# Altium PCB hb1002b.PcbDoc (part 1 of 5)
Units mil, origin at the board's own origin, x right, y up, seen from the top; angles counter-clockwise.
Board outline 2756 x 3549 mil, 2 copper layers (Top Layer, Bottom Layer); 120 components, 136 nets, 498 pads, 328 vias.
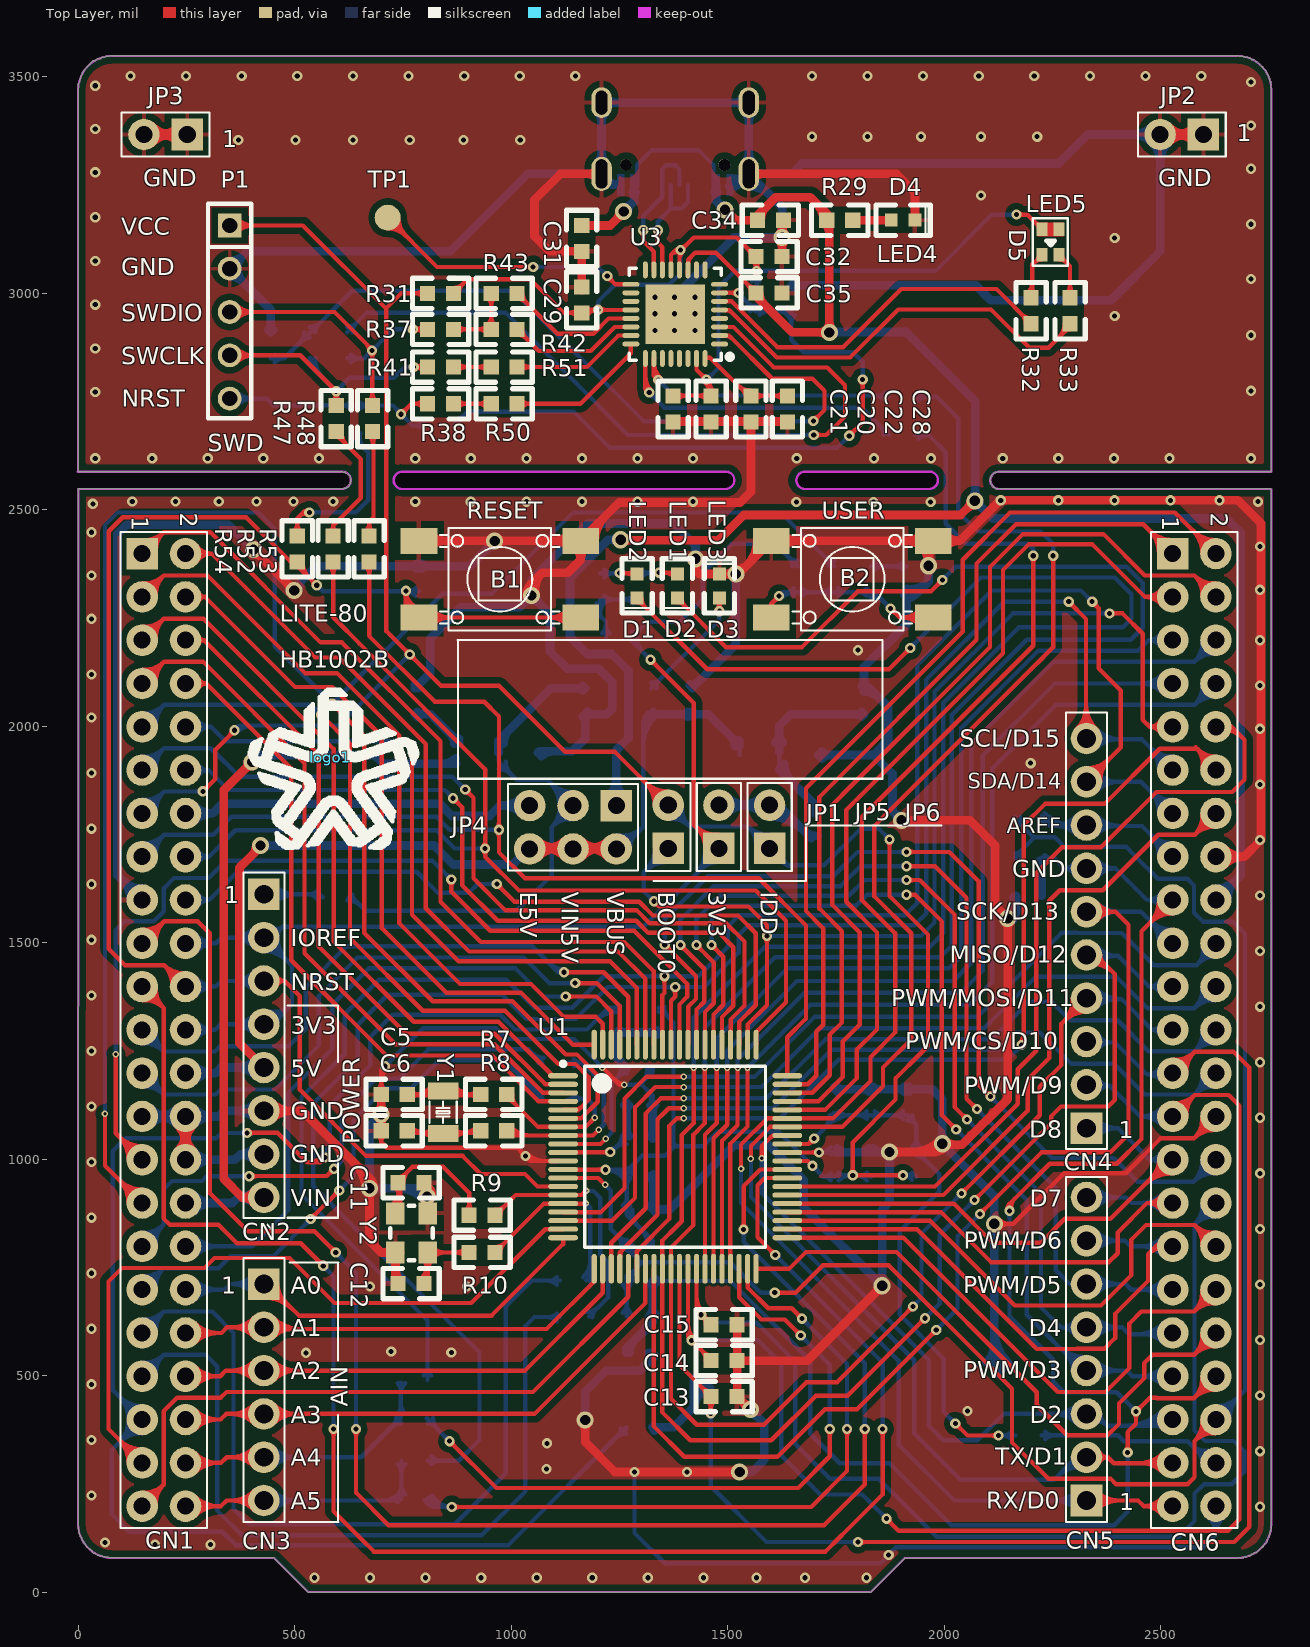
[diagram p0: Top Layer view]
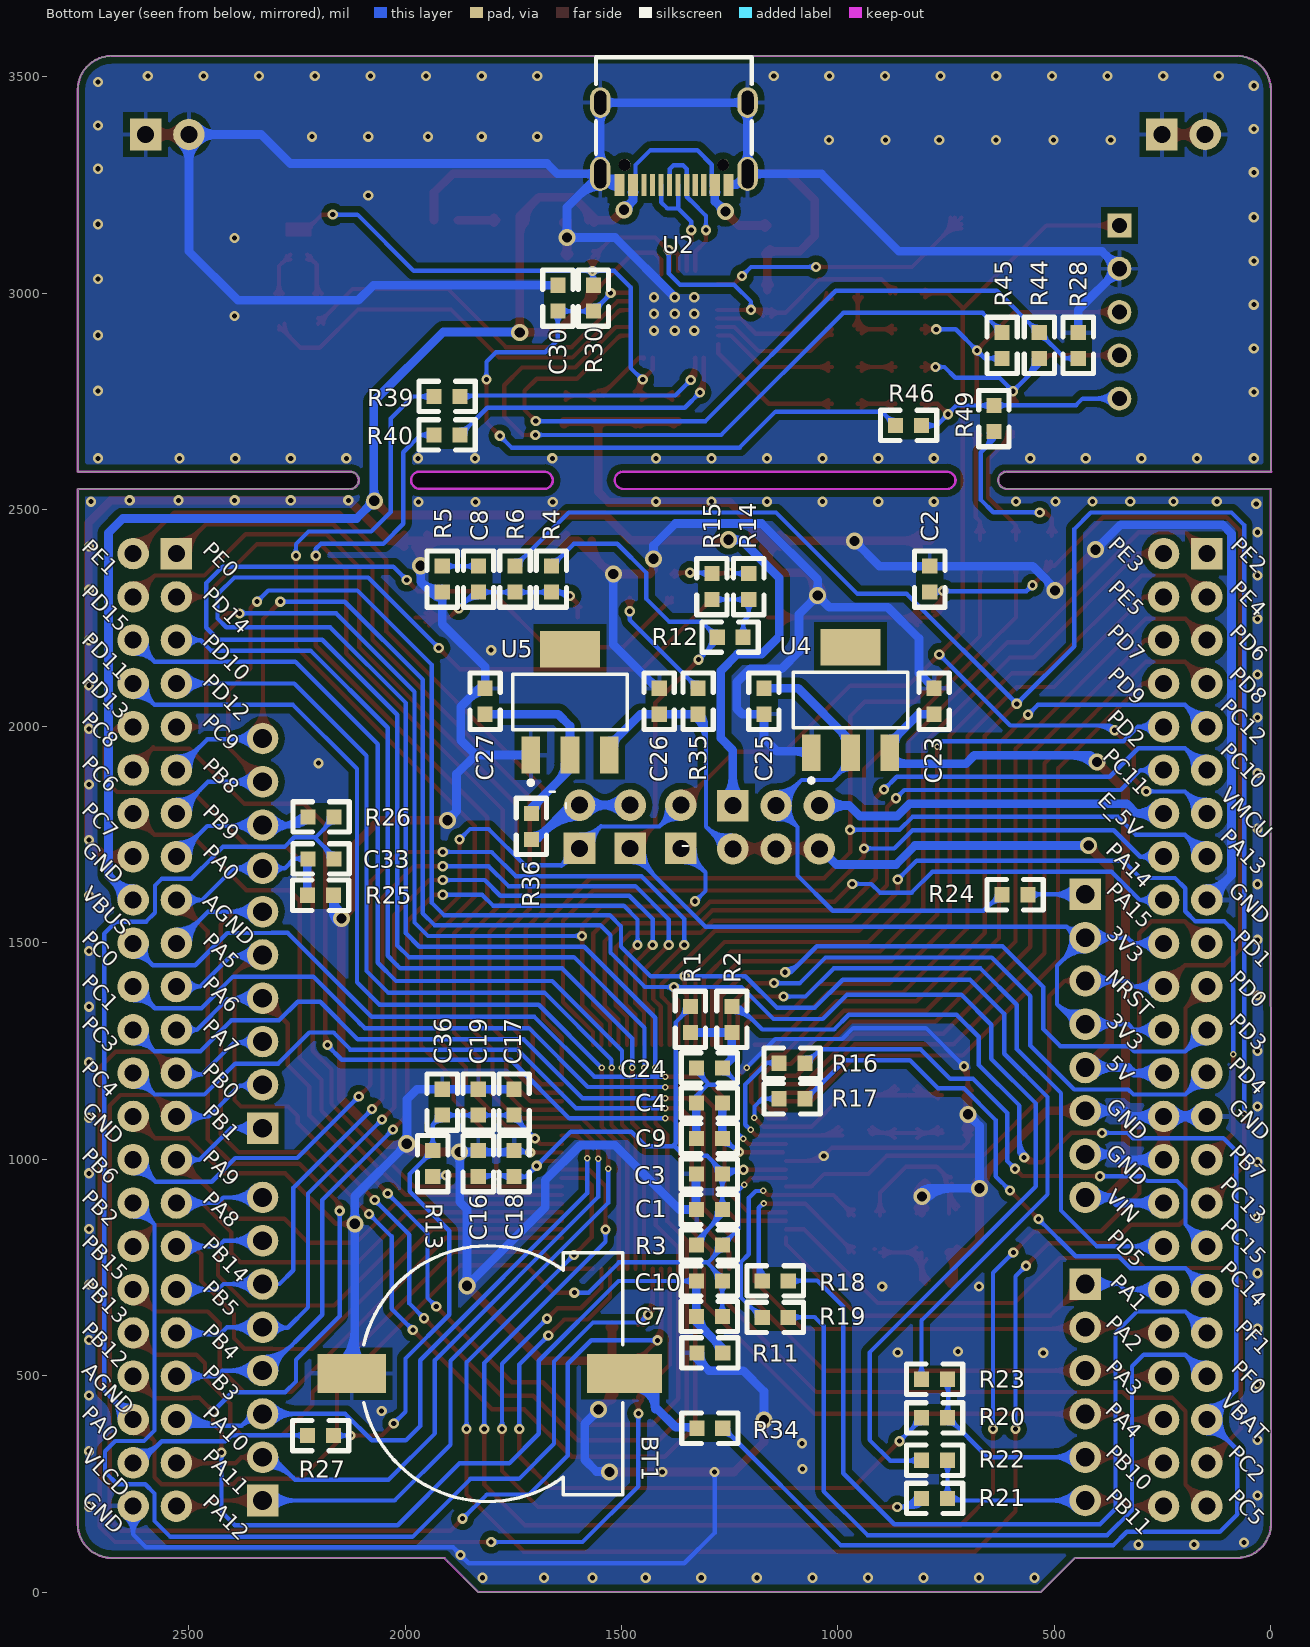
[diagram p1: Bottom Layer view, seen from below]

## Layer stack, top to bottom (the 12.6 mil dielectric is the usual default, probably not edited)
Top Layer: signal copper 1.4
Dielectric: dielectric 12.6, FR-4, Dk 4.8
Bottom Layer: signal copper 1.4

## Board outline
76,3549 2675,3549 2680,3549 2681,3548 2685,3548 2690,3548 2691,3547 2693,3547 2695,3547 2696,3546 2697,3545 2700,3545 2702,3545 2703,3544 2704,3543 2706,3543 2708,3543 2709,3542 2711,3540 2713,3540 2716,3540 2718,3538 2721,3535 2722,3535 2723,3535 2726,3532 2730,3528 2733,3525 2735,3523 2736,3523 2736,3521 2737,3520 2740,3517 2742,3515 2744,3513 2744,3511 2746,3509 2747,3508 2747,3506 2747,3505 2749,3503 2750,3502 2750,3499 2750,3498 2752,3496 2752,3494 2752,3492 2753,3491 2754,3490 2754,3488 2754,3486 2755,3485 2755,3482 2755,3477 2756,3476 2756,2588 2122,2588 2121,2587 2120,2587 2119,2586 2118,2586 2117,2586 2116,2585 2115,2584 2114,2583 2112,2581 2110,2579 2109,2578 2109,2577 2109,2576 2108,2575 2107,2574 2107,2573 2107,2570 2107,2567 2107,2565 2108,2564 2108,2561 2108,2560 2109,2559 2110,2558 2110,2557 2111,2557 2113,2555 2114,2554 2114,2552 2117,2552 2120,2549 2122,2549 2126,2549 2127,2549 2128,2548 2129,2549 2755,2549 2756,2549 2756,161 2756,148 2755,147 2755,143 2755,141 2754,140 2752,138 2752,135 2752,132 2751,131 2750,130 2750,127 2750,126 2748,124 2747,123 2747,122 2747,120 2746,119 2746,117 2743,114 2742,113 2742,112 2741,111 2740,110 2739,109 2737,107 2737,106 2736,105 2731,100 2730,100 2727,97 2725,95 2722,92 2721,91 2718,91 2716,91 2714,89 2713,88 2712,88 2710,88 2708,86 2706,84 2704,84 2701,84 2700,83 2699,82 2696,82 2693,82 2692,81 2691,80 2686,80 2680,80 2679,79 2674,79 1909,79 1901,71 1830,0 1775,0 532,0 492,40 452,80 310,80 71,80 70,81 66,81 63,81 62,82 61,82 58,82 57,83 56,84 53,84 50,84 49,85 48,86 46,86 44,86 42,88 40,90 39,90 36,90 35,91 33,93 33,94 30,97 28,99 27,99 26,99 24,101 23,102 21,104 19,106 19,107 18,108 17,109 17,111 16,112 13,115 13,116 11,118 10,119 10,120 10,121 9,122 8,123 8,125 8,126 6,128 5,129 5,130 5,132 4,133 3,134 3,136 3,139 2,140 1,141 1,144 1,147 0,148 0,153 0,2549 608,2549 613,2549 614,2550 616,2550 618,2550 619,2551 620,2552 621,2552 622,2552 623,2553 626,2556 626,2557 626,2558 627,2559 629,2561 629,2564 630,2565 630,2568 630,2572 629,2573 629,2576 629,2577 627,2579 625,2581 625,2582 623,2582 619,2586 618,2587 616,2587 612,2587 611,2588 607,2588 0,2588 0,3464 0,3471 0,3481 0,3485 2,3487 4,3489 4,3491 4,3496 6,3498 6,3500 6,3502 8,3504 9,3505 9,3509 12,3512 14,3514 14,3516 17,3519 20,3522 24,3526 27,3529 27,3530 32,3535 34,3537 38,3537 40,3537 42,3539 45,3542 46,3542 52,3542 53,3543 55,3545 57,3545 61,3545 64,3548 71,3548 74,3548 75,3549
cut-out: 1678,2549.67 1966.59,2549.67 ccw(c1966.59,2569.35) 1966.59,2589.04 1678,2589.04 ccw(c1678,2569.35)
cut-out: 746.97,2548.63 1495,2548.63 ccw(c1495,2568.31) 1495,2588 746.97,2588 ccw(c746.97,2568.31)

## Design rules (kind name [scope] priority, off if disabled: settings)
Clearance [(IsPad and InComponent('U1'))] p1: gap=7
Clearance Clearance_poly [(InPolygon)] p2: gap=15
Clearance Clearance_CN [(IsPad and InComponent('CN1','CN4','U2'))] p3: gap=6
Clearance Clearance_Pad [All] p4: gap=8
ComponentClearance [All] p1: gap=0 collisioncheckmode=3 verticalgap=0 showdistances=FALSE
HoleSize [All] p1: absolutevalues=TRUE maxlimit=130 minlimit=1 maxpercent=80.000 minpercent=20.000
MinimumSolderMaskSliver [All] p1: minsoldermaskwidth=0
PolygonConnect PolygonConnect_Pads [IsPad] p1: connectstyle=Relief reliefconductorwidth=10 reliefentries=4 polygonreliefangle="90 Angle"
PolygonConnect [All] p2: connectstyle=Direct reliefconductorwidth=10 reliefentries=4 polygonreliefangle="90 Angle"
RoutingVias [All] p1: holewidth=12 width=20 viastyle="Through Hole" minholewidth=10 minwidth=18 maxholewidth=300 maxwidth=500
SilkToSilkClearance [All] p1: silktosilkclearance=0
SilkscreenOverComponentPads [IsPad] p1: minsilkscreentomaskgap=0
SolderMaskExpansion [All] p1: expansion=4
TestPointUsage [All] p1: valid=0 allowmultiple=FALSE
Testpoint [All] p1: side=3 testpointundercomponent=TRUE minsize=40 maxsize=100 preferedsize=60 minholesize=0 maxholesize=40 preferedholesize=32 testpointgrid=1 style=297 order=0-112345678
Width [All] p1: maxlimit=20 minlimit=8 preferedwidth=10
19 further rules are at their usual default settings.

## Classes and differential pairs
net class PF[0..1]: PF0 PF1
net class PE[0..5]: PE0 PE1 PE2 PE3 PE4 PE5
net class PD[0..15]: PD0 PD1 PD2 PD3 PD4 PD5 PD6 PD7 PD8 PD9 PD10 PD11 PD12 PD13 PD14 PD15
net class PC[0..15]: PC0 PC1 PC2 PC3 PC4 PC5 PC6 PC7 PC8 PC9 PC10 PC11 PC12 PC13 PC14 PC15
net class PB[0..15]: PB0 PB1 PB2 PB3 PB4 PB5 PB6 PB7 PB8 PB9 PB10 PB11 PB12 PB13 PB14 PB15
net class PA[0..15]: PA0 PA1 PA2 PA3 PA4 PA5 PA6 PA7 PA8 PA9 PA10 PA11 PA12 PA13 PA14 PA15
component class power: BT1 C23 C25 C26 C27 D3 JP2 JP3 JP4 JP5 JP6 R34 R35 R36 U4 U5
component class mcu: B1 B2 C1 C2 C3 C4 C5 C6 C7 C8 C9 C10 C11 C12 C13 C14 C15 C16 C17 C18 C19 C24 C36 D1 D2 JP1 logo1 R1 R2 R3 R4 R5 R6 R7 R8 R9 R10 R11 R12 R13 R14 R15 R52 R53 R54 U1 Y1 Y2
component class arduino_extension_interfaces: C33 CN1 CN2 CN3 CN4 CN5 CN6 R16 R17 R18 R19 R20 R21 R22 R23 R24 R25 R26 R27
component class hed_link: C20 C21 C22 C28 C29 C30 C31 C32 C34 C35 C36 D4 D5 P1 R28 R29 R30 R31 R32 R33 R37 R38 R39 R40 R41 R42 R43 R44 R45 R46 R47 R48 R49 R50 R51 TP1 TP6 U2 U3

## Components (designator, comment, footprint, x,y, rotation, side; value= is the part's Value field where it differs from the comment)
B1 "SW-PUSH-CMS_BLACK" SWI_WEALTHMETAL_TD-0341_4P_BLACK 974,2340 r270 top locked
B2 "SW-PUSH-CMS_BLUE" SWI_WEALTHMETAL_TD-0341_4P_BLUE 1788,2340 r270 top locked
BT1 "" CR1220 1493,505 r180 bottom
C1 "4.7u" 0603 1327,884 r180 bottom
C2 "0.1u" 0603 788,2310 r90 bottom
C3 "0.1u" 0603 1327,966 r180 bottom
C4 "0.1u" 0603 1267,1130 r0 bottom
C5 "22p" 0603 700,1150 r0 top
C6 "22p" 0603 700,1066 r0 top
C7 "DNP" 0603 1327,637 r180 bottom
C8 "0.1u" 0603 1830,2370 r270 bottom
C9 "1u" 0603 1267,1048 r0 bottom
C10 "DNP" 0603 1327,719 r180 bottom
C11 "DNP" 0603 739,946 r0 top
C12 "DNP" 0603 799,713 r180 top
C13 "DNP" 0603 1462,452 r0 top
C14 "DNP" 0603 1462,535 r0 top
C15 "DNP" 0603 1462,618 r0 top
C16 "4.7u" 0603 1831,960 r90 bottom
C17 "DNP" 0603 1748,1102 r90 bottom
C18 "0.1u" 0603 1748,960 r90 bottom
C19 "DNP" 0603 1831,1102 r90 bottom
C20 "1u" 0603 1462,2703 r90 top
C21 "10n" 0603 1374,2703 r90 top
C22 "4.7u" 0603 1554,2703 r90 top
C23 "10u" 0603 778,2088 r270 bottom
C24 "0.1u" 0603 1327,1211 r180 bottom
C25 "10u" 0603 1171,2028 r90 bottom
C26 "10u" 0603 1413,2088 r270 bottom
C27 "10u" 0603 1815,2088 r270 bottom
C28 "0.1u" 0603 1638,2703 r90 top
C29 "0.1u" 0603 1163,2955 r90 top
C30 "0.1u" 0603 1647,2959 r90 bottom
C31 "10u" 0603 1163,3097 r90 top
C32 "1u" 0603 1566,3085 r0 top
C33 "DNP" 0603 2224,1694 r180 bottom
C34 "0.1u" 0603 1629,3169 r180 top
C35 "1u" 0603 1566,3001 r0 top
C36 "DNP" 0603 1914,1102 r90 bottom
CN1 "Header 23x2" HEADER_1X23_2.54 148,2399 r270 top locked
CN2 "Socket 8x1" HEADER_1X8_2.54 429,1262 r270 top locked
CN3 "Socket 6x1" HEADER_1X6-2.54 429,462 r270 top locked
CN4 "Socket 10x1" HEADER_1X10_2.54 2329,1522 r90 top locked
CN5 "Socket 8x1" HEADER_1X8_2.54 2329,562 r90 top locked
CN6 "Header 23x2" HEADER_1X23_2.54 2528,2399 r270 top locked
D1 "LED_B" "0603 - p" 1291,2352 r270 top locked
D2 "LED_P" "0603 - p" 1384,2352 r270 top locked
D3 "LED_R" "0603 - P" 1481,2297 r90 top locked
D4 "LED_R" "0603 - p" 1878,3169 r0 top
D5 "LD_BICOLOR_CMS" LED-SMD_4P_1615 2226,3089 r90 top
JP1 "Shunt Fitted" HEADER_1X2_2.54 1363,1768 r90 top locked
JP2 "Shunt Fitted" CON_SAMTEC_TSW-102-07-G-S 2549,3367 r180 top
JP3 "Shunt Fitted" CON_SAMTEC_TSW-102-07-G-S 202,3367 r180 top
JP4 "Shunt Fitted 1-2" HEADER_2X3_2.54 1243,1817 r180 top locked
JP5 "Shunt Fitted" HEADER_1X2_2.54 1480,1768 r90 top locked
JP6 "Shunt Fitted" HEADER_1X2_2.54 1597,1768 r90 top locked
logo1 "logo" 华大电子LOGO 582,1929 r0 top
P1 "SWD" HED_5_4_2.5 350,3157 r270 top locked
R1 "0R" 0603 1341,1293 r90 bottom
R2 "DNP" 0603 1245,1353 r270 bottom
R3 "0R" 0603 1267,802 r0 bottom
R4 "4.7k" 0603 1662,2310 r90 bottom
R5 "100R" 0603 1914,2370 r270 bottom
R6 "0R" 0603 1746,2370 r270 bottom
R7 "0R" 0603 990,1150 r180 top
R8 "0R" 0603 990,1066 r180 top
R9 "DNP" 0603 903,871 r0 top
R10 "DNP" 0603 903,785 r0 top
R11 "0R" 0603 1266,553 r0 bottom
R12 "0R" 0603 1219,2206 r0 bottom
R13 "0R" 0603 1936,1020 r270 bottom
R14 "510R" 0603 1206,2353 r270 bottom
R15 "510R" 0603 1291,2353 r270 bottom
R16 "DNP" 0603 1076,1222 r0 bottom
R17 "DNP" 0603 1076,1140 r0 bottom
R18 "0R" 0603 1115,719 r0 bottom
R19 "0R" 0603 1115,635 r0 bottom
R20 "0R" 0603 747,403 r0 bottom
R21 "0R" 0603 747,217 r0 bottom
R22 "DNP" 0603 807,305 r180 bottom
R23 "DNP" 0603 807,492 r180 bottom
R24 "DNP" 0603 621,1611 r180 bottom
R25 "0R" 0603 2225,1610 r180 bottom
R26 "0R" 0603 2164,1791 r0 bottom
R27 "0R" 0603 2165,362 r0 bottom
R28 "DNP" 0603 445,2910 r270 bottom
R29 "1K" 0603 1729,3169 r0 top
R30 "DNP" 0603 1565,3019 r270 bottom
R31 "DNP" 0603 807,3000 r0 top
R32 "330R" 0603 2201,2930 r90 top
R33 "330R" 0603 2291,2930 r90 top
R34 "0R" 0603 1266,379 r0 bottom
R35 "1K" 0603 1323,2088 r270 bottom
R36 "0R" 0603 1708,1739 r90 bottom
R37 "0R" 0603 867,2917 r180 top
R38 "0R" 0603 867,2745 r180 top
R39 "0R" 0603 1873,2762 r0 bottom
R40 "0R" 0603 1873,2673 r0 bottom
R41 "0R" 0603 867,2830 r180 top
R42 "150R" 0603 1014,2917 r180 top
R43 "150R" 0603 1014,3000 r180 top
R44 "DNP" 0603 535,2910 r270 bottom
R45 "DNP" 0603 621,2910 r270 bottom
R46 "DNP" 0603 867,2695 r180 bottom
R47 "0R" 0603 596,2681 r90 top
R48 "0R" 0603 680,2681 r90 top
R49 "0R" 0603 640,2681 r90 bottom
R50 "150R" 0603 1014,2745 r180 top
R51 "150R" 0603 1014,2830 r180 top
R52 "10R" 0603 589,2440 r270 top
R53 "10R" 0603 672,2440 r270 top
R54 "10R" 0603 506,2440 r270 top
TP1 "TEST_POINT" TEST_POINT 720,3213 r90 top
U1 "MCU" LQFP-80N-12X12 1379,1006 r0 top locked
U2 "TYPE-C-16P" HED-KH-TYPE-C-16P 1208.84,3276 r0 bottom
U3 "MCU" HED-QFN-32_5x5x05P 1379,2952 r90 top
U4 "AMS1117-5V" SOT223 971,2061 r180 bottom locked
U5 "AMS1117-3V3" SOT223 1619,2056 r180 bottom locked
Y1 "YST310S" CRY_3215SA_2P 843,1109 r270 top
Y2 "DNP" "3.2*2.5*0.7 OSC" 770,830 r270 top

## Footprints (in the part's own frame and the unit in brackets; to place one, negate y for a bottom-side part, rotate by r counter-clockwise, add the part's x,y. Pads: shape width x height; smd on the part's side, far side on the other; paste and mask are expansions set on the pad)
"3.2*2.5*0.7 OSC" [mm]
  rect 1.3x1.1 smd: 1(-1.15,-0.95) 2(1.15,-0.95) 3(1.15,0.95) 4(-1.15,0.95)
  round 0.25 on Top Overlay: 12(-2.075,-1.375)
  silkscreen extent -1.6,-1.25 1.6,1.25, body extent -1.6,-1.28 1.6,1.25, height 0.7
0603 [mil]
  rect 35x35 smd: 1(0,0) 2(60,0)
  silkscreen extent -35,-35 95,35
"0603 - p" [mil]
  rect 30x30 smd: 1(0,0) 2(55,0)
  silkscreen extent -35,-35 90,35, body extent 1,-15 60,15, height 10
"0603 - P" [mil]
  rect 30x30 smd: 1(0,0) 2(55,0)
  silkscreen extent -35,-35 90,35, body extent 1,-15 60,15, height 10
CON_SAMTEC_TSW-102-07-G-S [mm]
  rect 1.85x1.85 / inner round 1.85 / far side rect 1.85x1.85 hole 1: 1(-1.27,0)
  round 1.85 hole 1: 2(1.27,0)
  silkscreen extent -2.58,-1.3 2.58,1.3, body extent -2.67,-1.3 2.58,1.3, height 8.38
CR1220 [mm]
  rect 4.4x2.3 smd: 1(0,0)
  rect 4x2.3 smd: 2(-16,0)
  silkscreen extent -15.31,-7.5 -0.1,7.5
CRY_3215SA_2P [mm]
  rect 1x1.8 smd: 1(-1.25,0) 2(1.25,0)
  silkscreen extent -0.63,-0.8 0.63,0.8, body extent -1.65,-0.8 1.65,0.8, height 0.9
HEADER_1X2_2.54 [mm]
  rect 1.85x1.85 / inner round 1.85 / far side rect 1.85x1.85 hole 1: 1(-1.27,0)
  round 1.85 hole 1: 2(1.27,0)
  silkscreen extent -2.58,-1.3 2.58,1.3, body extent -2.67,-1.3 2.58,1.3, height 8.38
HEADER_1X6-2.54 [mm]
  rect 1.85x1.85 / inner round 1.85 / far side rect 1.85x1.85 hole 1.1: 1(-6.35,0)
  round 1.85 hole 1.1: 2(-3.81,0) 3(-1.27,0) 4(1.27,0) 5(3.81,0) 6(6.35,0)
  silkscreen extent -7.88,-1.2 7.62,1.2, body extent -7.88,-1.21 7.88,1.21, height 8.51
HEADER_1X8_2.54 [mm]
  rect 1.85x1.85 / inner round 1.85 / far side rect 1.85x1.85 hole 1.1: 1(-8.89,0)
  round 1.85 hole 1.1: 2(-6.35,0) 3(-3.81,0) 4(-1.27,0) 5(1.27,0) 6(3.81,0) 7(6.35,0) 8(8.89,0)
  silkscreen extent -10.16,-1.2 10.08,1.2, body extent -10.42,-1.21 10.42,1.21, height 8.51
HEADER_1X10_2.54 [mm]
  rect 1.85x1.85 / inner round 1.85 / far side rect 1.85x1.85 hole 1.1: 1(-11.43,0)
  round 1.85 hole 1.1: 2(-8.89,0) 3(-6.35,0) 4(-3.81,0) 5(-1.27,0) 6(1.27,0) 7(3.81,0) 8(6.35,0) 9(8.89,0) 10(11.43,0)
  silkscreen extent -12.65,-1.2 12.96,1.2, body extent -12.96,-1.21 12.96,1.21, height 8.51
HEADER_1X23_2.54 [mm]
  rect 1.85x1.85 / inner round 1.85 / far side rect 1.85x1.85 hole 1: 1(0,0)
  round 1.85 hole 1: 2(0,2.54) 3(2.54,0) 4(2.54,2.54) 5(5.08,0) 6(5.08,2.54) 7(7.62,0) 8(7.62,2.54) 9(10.16,0) 10(10.16,2.54) 11(12.7,0) 12(12.7,2.54) 13(15.24,0) 14(15.24,2.54) 15(17.78,0) 16(17.78,2.54) 17(20.32,0) 18(20.32,2.54) 19(22.86,0) 20(22.86,2.54) 21(25.4,0) 22(25.4,2.54) 23(27.94,0) 24(27.94,2.54) 25(30.48,0) 26(30.48,2.54) 27(33.02,0) 28(33.02,2.54) 29(35.56,0) 30(35.56,2.54) 31(38.1,0) 32(38.1,2.54) 33(40.64,0) 34(40.64,2.54) 35(43.18,0) 36(43.18,2.54) 37(45.72,0) 38(45.72,2.54) 39(48.26,0) 40(48.26,2.54) 41(50.8,0) 42(50.8,2.54) 43(53.34,0) 44(53.34,2.54) 45(55.88,0) 46(55.88,2.54)
  silkscreen extent -1.27,-1.27 57.15,3.81, body extent -1.27,-1.4 57.15,3.81, height 8.38
HEADER_2X3_2.54 [mm]
  rect 1.85x1.85 / inner round 1.85 / far side rect 1.85x1.85 hole 1: 1(0,0)
  round 1.85 hole 1: 2(0,2.54) 3(2.54,0) 4(2.54,2.54) 5(5.08,0) 6(5.08,2.54)
  silkscreen extent -1.27,-1.27 6.35,3.81, body extent -1.27,-1.33 8.89,3.87, height 8.38
HED-KH-TYPE-C-16P [mm]
  oval 1.2x2 hole 0.7 slot 1.7 at 90 deg: 1(0,0) 2(8.64,0)
  oval 1.2x1.8 hole 0.7 slot 1.4 at 90 deg: 3(0,-4.18) 4(8.64,-4.18)
  rect 0.3x1.3 smd: A1(0.97,0.65) A4(1.77,0.65) A5(3.07,0.65) A6(4.07,0.65) A7(4.57,0.65) A8(5.57,0.65) A9(6.87,0.65) A12(7.67,0.65) B1(7.37,0.65) B4(6.57,0.65) B5(6.07,0.65) B6(5.07,0.65) B7(3.57,0.65) B8(2.57,0.65) B9(2.07,0.65) B12(1.27,0.65)
  round 0.7 hole 0.7 unplated: ""(1.43,-0.53) ""(7.21,-0.53)
  silkscreen extent -0.25,-6.84 8.89,-1.19
HED-QFN-32_5x5x05P [mm]
  oval 0.28x1 smd: 1(-1.75,-2.6) 2(-1.25,-2.6) 3(-0.75,-2.6) 4(-0.25,-2.6) 5(0.25,-2.6) 6(0.75,-2.6) 7(1.25,-2.6) 8(1.75,-2.6) 17(1.75,2.6) 18(1.25,2.6) 19(0.75,2.6) 20(0.25,2.6) 21(-0.25,2.6) 22(-0.75,2.6) 23(-1.25,2.6) 24(-1.75,2.6)
  oval 1x0.28 smd: 9(2.6,-1.75) 10(2.6,-1.25) 11(2.6,-0.75) 12(2.6,-0.25) 13(2.6,0.25) 14(2.6,0.75) 15(2.6,1.25) 16(2.6,1.75) 25(-2.6,1.75) 26(-2.6,1.25) 27(-2.6,0.75) 28(-2.6,0.25) 29(-2.6,-0.25) 30(-2.6,-0.75) 31(-2.6,-1.25) 32(-2.6,-1.75)
  rect 3.5x3.5 smd: 33(0,0)
  silkscreen extent -2.7,-3.35 2.7,2.7
HED_5_4_2.5 [mil]
  rect 55x55 hole 35: 1(0,0)
  round 55 hole 35: 2(100,0) 3(200,0) 4(300,0) 5(400,0)
  silkscreen extent -50,-50 445,50
LED-SMD_4P_1615 [mm]
  rect 0.8x0.65 smd: 1(0,0) 2(1.5,0) 3(0,-1) 4(1.5,-1)
  silkscreen extent -0.64,-1.52 2.16,0.54
LQFP-80N-12X12 [mm] "TSQFP, 80-Leads, Body 14.2x14.2mm (max), Pitch 0.50mm, IPC Medium Density"
  oval 1.75x0.3 smd: 1(-6.575,4.75) 2(-6.575,4.25) 3(-6.575,3.75) 4(-6.575,3.25) 5(-6.575,2.75) 6(-6.575,2.25) 7(-6.575,1.75) 8(-6.575,1.25) 9(-6.575,0.75) 10(-6.575,0.25) 11(-6.575,-0.25) 12(-6.575,-0.75) 13(-6.575,-1.25) 14(-6.575,-1.75) 15(-6.575,-2.25) 16(-6.575,-2.75) 17(-6.575,-3.25) 18(-6.575,-3.75) 19(-6.575,-4.25) 20(-6.575,-4.75) 41(6.575,-4.75) 42(6.575,-4.25) 43(6.575,-3.75) 44(6.575,-3.25) 45(6.575,-2.75) 46(6.575,-2.25) 47(6.575,-1.75) 48(6.575,-1.25) 49(6.575,-0.75) 50(6.575,-0.25) 51(6.575,0.25) 52(6.575,0.75) 53(6.575,1.25) 54(6.575,1.75) 55(6.575,2.25) 56(6.575,2.75) 57(6.575,3.25) 58(6.575,3.75) 59(6.575,4.25) 60(6.575,4.75)
  oval 0.3x1.75 smd: 21(-4.75,-6.575) 22(-4.25,-6.575) 23(-3.75,-6.575) 24(-3.25,-6.575) 25(-2.75,-6.575) 26(-2.25,-6.575) 27(-1.75,-6.575) 28(-1.25,-6.575) 29(-0.75,-6.575) 30(-0.25,-6.575) 31(0.25,-6.575) 32(0.75,-6.575) 33(1.25,-6.575) 34(1.75,-6.575) 35(2.25,-6.575) 36(2.75,-6.575) 37(3.25,-6.575) 38(3.75,-6.575) 39(4.25,-6.575) 40(4.75,-6.575) 61(4.75,6.575) 62(4.25,6.575) 63(3.75,6.575) 64(3.25,6.575) 65(2.75,6.575) 66(2.25,6.575) 67(1.75,6.575) 68(1.25,6.575) 69(0.75,6.575) 70(0.25,6.575) 71(-0.25,6.575) 72(-0.75,6.575) 73(-1.25,6.575) 74(-1.75,6.575) 75(-2.25,6.575) 76(-2.75,6.575) 77(-3.25,6.575) 78(-3.75,6.575) 79(-4.25,6.575) 80(-4.75,6.575)
  silkscreen extent -6.7,-5.3 5.3,5.57, body extent -6,-6 6,6, height 1.4
SOT223 [mm] "SOT-223/SC-73; 4 Leads; Body 6.7 x 7.3 mm, inc. leads (LxW max)"
  rect 1.1x2.15 smd: 1(-2.3,-3.1) 2(0,-3.1) 3(2.3,-3.1)
  rect 3.5x2.15 smd: 4(0,3.1)
  silkscreen extent -3.35,-4.85 3.35,1.63
SWI_WEALTHMETAL_TD-0341_4P_BLACK [mm]
  rect 1.52x2.16 smd: 1(-2.25,-4.75) 2(-2.25,4.75) 3(2.25,-4.75) 4(2.25,4.75)
  silkscreen extent -3,-3.5 3,3.5, body extent -3,-5.15 3,5.15, height 7.55
SWI_WEALTHMETAL_TD-0341_4P_BLUE [mm]
  rect 1.52x2.16 smd: 1(-2.25,-4.75) 2(-2.25,4.75) 3(2.25,-4.75) 4(2.25,4.75)
  silkscreen extent -3,-3.5 3,3.5, body extent -3,-5.15 3,5.15, height 7.55
TEST_POINT [mil]
  round 60 smd: 1(-38,5)
华大电子LOGO [mil]
  silkscreen extent -187,-211 203,157

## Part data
B1: library part MCD-00001, "Non-Open Push-Button 0.1A 24V"
B2: library part MCD-00002, "Non-Open Push-Button 0.1A 24V"
BT1: library part Battery, "Multicell Battery"
C1 C11 C12 C13 C14 C15 C16 C17 C19 C36: library part MCD-00009, "Capacitor, MLCC, 4.7uF, 16V, X5R, 10%, 0603, T=0.8mm"
C2: library part Capacitor, "Capacitor, MLCC, 100nF, 16V, X7R, 10%, 0603, T=0,8mm"
C3 C4 C7 C9 C10 C18 C20 C21 C28 C29 C30 C32 C33 C35: library part MCD-00211, "Capacitor, MLCC, 100nF, 16V, X7R, 10%, 0603, T=0,8mm"
C5 C6: library part Capacitor, "Capacitor,5.6pF,0.1pF,16V,NPO,0603"
C8: library part MCD-00211, "贴片电容"
C22 C34: library part "0603 100nF 10% 50V", "贴片电容"
C23 C24 C25 C26 C27: library part MCD-00014, "Capacitor, MLCC, 10uF, 25V, X5R, 10%, 0805, T=0,85mm"
C31: library part "0603 4.7uF 10% 16V", "贴片电容"
CN1 CN6: "Header, 19x2, 2,54mm, VR, TH, Height 5.84mm/10.16mm"
CN2 CN5: "Socket, 8x1, 2.54mm, VR, TH, Height 8.51mm/10mm"
CN3: "Socket, 6x1, 2.54mm, VR, TH, Height 8.51mm/10mm"
CN4: "Socket, 10x1, 2.54mm, VR, TH, Height 8.51mm/10mm"
D1 D2 D3: library part LED1, "Typical RED GaAs LED"
D4: library part LED3, "Typical BLUE SiC LED"
D5: "LED Bicolor"
JP1 JP5 JP6: library part "Jumper_Header 2x1 Fitted", "Header, 2x1, 2,54mm, VR, TH, Height 5.84mm/2.54mm - Shunt Fitted by default"
JP2 JP3: library part MCD-00683, "Header, 2x1, 2,54mm, VR, TH, Height 5.84mm/2.54mm - Shunt Fitted by default"
JP4: library part "Jumper_Header 4x2 Fitted 1-2", "Header, 4x2, 2,54mm, VR, TH, Height 5.84mm/2.54mm - Shunt Fitted 1-2"
R1 R2 R3 R4 R5 R6 R7 R8 R9 R10 R11 R12 R13 R14 R15 R16 R17 R18 R19 R20 R21 R22 R23 R24 R25 R26 R27 R29 R30 R31 R32 R33 R34 R35 R36 R37 R38 R39 R40 R41: library part Res2, "贴片电阻"
R28 R42 R43 R44 R45 R46 R47 R48 R49 R50 R51 R52 R53 R54: library part Res, "贴片电阻"
U1: library part LQFP80
U2: library part KH-TYPE-C-16P, "TYPE-C USB接口"
U3: library part CIU98-H
U4 U5: "IC REG LDO 5V 0.8A SOT223"
Y1: library part XTAL_32K_NX3215SA, "32.768k无源晶振"
Y2: library part XTAL_4

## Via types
v1: diameter 23.62, hole 11.81, Top Layer to Bottom Layer, tented both sides, 276 vias
v2: diameter 39.37, hole 23.62, Top Layer to Bottom Layer, tented both sides, 27 vias
v3: diameter 15, hole 8, Top Layer to Bottom Layer, tented both sides, 25 vias

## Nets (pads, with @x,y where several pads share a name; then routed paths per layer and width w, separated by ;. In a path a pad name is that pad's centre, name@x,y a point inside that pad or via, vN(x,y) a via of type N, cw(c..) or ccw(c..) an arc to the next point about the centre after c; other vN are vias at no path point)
AGND: C7.1 C10.1 C33.1 CN4.7 CN6.17 CN6.40 R11.1 R25.1 | length 5385.3
  Top Layer w10: v1@2146.28,885.91 ccw(c2135.61,897) 2151,897 ; v1@2148.1,879.68 cw(c2162.41,886.18) 2151.29,897.29 ; v1(2151,881) 2151,897 ; 2152,898 2161.5,907.5 ; v1@2155.72,885.91 cw(c2166.39,897) 2151,897 ; v1@2157.2,883.82 cw(c2176.44,892.56) 2161.5,907.5 ; v1@2419.18,327.82 ccw(c2407.56,339.44) 2424,339.44 ccw(c2440.44,339.44) v1@2428.82,327.82 ; v1(2424,323) 2424,357 2424,370 2443.5,389.5 2443.5,417.5 2475,449 2491,449 ; v1@2438.18,413.18 cw(c2425.35,400.35) 2443.5,400.35 ; v1@2443,424.81 ccw(c2443,443.67) 2456.33,430.33 ; 2443.5,402.76 cw(c2458.24,402.76) v1@2447.82,413.18 ; v1@2449.81,418 cw(c2463.84,418) 2453.92,427.92 ; 2456,1122 2456,1131 ; 2491.3,448.42 2577.42,448.42 ; CN6.17@2496.58,1599 cw(c2420.73,1599) 2474.37,1545.37 cw(c2528,1491.73) CN6.17@2528,1567.58 ; CN6.17@2506.58,1599 cw(c2454.88,1599) 2491.44,1562.44 cw(c2528,1525.88) CN6.17@2528,1577.58 ; CN6.17@2528,1599 2456,1527 2456,1131 ; CN6.40@2596.61,497.67 cw(c2530.95,494.89) 2577.42,448.42 ; CN6.40@2606.6,498.09 cw(c2561.84,496.2) 2593.52,464.52 cw(c2625.2,432.84) CN6.40@2627.09,477.6 ; CN6.40@2626.67,467.61 ccw(c2623.89,401.95) 2577.42,448.42 ; CN6.40@2628,499 2577.42,448.42 ; 2151,897 2161.5,907.5 ; 2161.5,907.5 2244,990 2399,990 2456,1047 2456,1131
  Bottom Layer w10: C10.1@1327,719 1507,719 1691,535 1691,366 1759,298 1874,298 2017,155 2393,155 2424,186 v1@2424,324 ; C10.1@1335.84,710.16 cw(c1357.18,688.82) 1357.18,719 cw(c1357.18,749.18) C10.1@1335.84,727.84 ; v1@2146.18,876.18 cw(c2134.56,864.56) 2151,864.56 cw(c2167.44,864.56) v1@2155.82,876.18 ; v1(2151,881) 2151,638 2252,537 2252,487 2277,462 2399,462 v1(2443,418) ; C33.1@2222,1692 2226,1692 2226,1694 2256,1694 2278,1672 ; C33.1@2232.84,1685.16 cw(c2254.18,1663.82) 2254.18,1694 cw(c2254.18,1724.18) C33.1@2232.84,1702.84 ; CN4.7@2300.94,1657.87 ccw(c2278,1646.32) 2278,1672 ; CN4.7@2300.94,1686.13 cw(c2278,1697.68) 2278,1672 ; CN4.7@2345.47,1658.3 cw(c2374.67,1634.01) 2374.67,1672 cw(c2374.67,1709.99) CN4.7@2345.47,1685.7 ; CN4.7@2353.15,1651.91 cw(c2396,1616.27) 2396,1672 ; CN4.7@2353.15,1692.09 ccw(c2396,1727.73) 2396,1672 ; v1@2419.18,318.18 cw(c2407.56,306.56) 2424,306.56 cw(c2440.44,306.56) v1@2428.82,318.18 ; v1@2436.19,418 ccw(c2419.75,418) 2431.37,429.63 ccw(c2443,441.25) v1@2443,424.81 ; CN6.17@2501.93,1581.46 ccw(c2469,1559.31) 2469,1599 ; CN6.17@2501.93,1616.54 cw(c2469,1638.69) 2469,1599 ; CN6.17@2510.23,1587.05 ccw(c2487.78,1571.95) 2487.78,1599 ccw(c2487.78,1626.05) CN6.17@2510.23,1610.95 ; CN6.17@2528,1599 2469,1599 ; 2278,1672 CN4.7@2329,1672 2396,1672 ; 2396,1672 2469,1599
  Bottom Layer w20: R11.1@1266,553 1266,563 1327,624 C7.1@1327,637 C10.1@1327,719 ; R11.1@1273.5,553 cw(c1315.74,553) 1285.87,582.87 ; 1305,602 ccw(c1270.01,637) C7.1@1319.5,637 ; C7.1@1321.7,642.3 ccw(c1308.89,655.11) 1327,655.11 ccw(c1345.11,655.11) C7.1@1332.3,642.3 ; C10.1@1321.7,713.7 cw(c1308.89,700.89) 1327,700.89 cw(c1345.11,700.89) C10.1@1332.3,713.7 ; C33.1@2218.7,1688.7 cw(c2201.06,1671.06) 2226,1671.06 ; R25.1@2219.7,1615.3 ccw(c2204.48,1630.52) 2226,1630.52 ; R25.1@2226,1609 C33.1@2226,1692
CMS_STATE: TP1.1 U3.17 | length 882.4
  Top Layer w10: TP1.1@715,3150 cw(c715,3089.64) 757.68,3132.32 cw(c800.36,3175) TP1.1@740,3175 ; TP1.1@715,3160 cw(c715,3123.79) 740.61,3149.39 cw(c766.21,3175) TP1.1@730,3175 ; TP1.1@715,3175 829,3061 v1(1051,3061) ; v1@1046.18,3056.18 ccw(c1034.56,3044.56) 1034.56,3061 ccw(c1034.56,3077.44) v1@1046.18,3065.82 ; v1@1222,3033.19 cw(c1222,3016.75) 1233.63,3028.37 cw(c1245.25,3040) v1@1228.81,3040 ; v1(1222,3040) 1241.1,3020.9 U3.17@1278.61,3020.9
  Bottom Layer w10: v1(1051,3061) 1201,3061 v1(1222,3040) ; v1@1055.82,3056.18 cw(c1067.44,3044.56) 1067.44,3061 cw(c1067.44,3077.44) v1@1055.82,3065.82 ; v1@1215.19,3040 ccw(c1198.75,3040) 1210.37,3051.63 ccw(c1222,3063.25) v1@1222,3046.81
EXTERN_5V: CN1.14 JP4.5 | length 1054.5
  Bottom Layer w10: JP4.5@1043,1817.24 1041.24,1819 JP4.5@1069,1819
  Bottom Layer w20: CN1.14@248,1799 311,1799 ; CN1.14@266.84,1780.48 cw(c311,1737.1) 311,1799 ; CN1.14@266.84,1817.52 ccw(c311,1860.9) 311,1799 ; 978.63,1817.24 cw(c978.63,1752.63) JP4.5@1024.32,1798.32 ; 979.81,1817.24 ccw(c979.81,1880.19) JP4.5@1024.32,1835.68 ; JP4.5@1043,1817.24 974.24,1817.24 950,1793 863,1793 835,1821 333,1821 311,1799
EXTERN_VLCD: C17.1 C19.1 C36.1 R13.1 R27.1 U1.52 | length 1885.4
  Top Layer w10: U1.52@1637.86,1035.53 1687.53,1035.53 v1(1700,1048) ; v1@1693.19,1048 cw(c1676.75,1048) 1688.37,1036.37 cw(c1700,1024.75) v1@1700,1041.19 ; v1@2026,383.19 cw(c2026,366.75) 2037.63,378.37 cw(c2049.25,390) v1@2032.81,390 ; v1(2026,390) 2054,362 v1(2126,362) v1@2127,362 ; v1@2121.18,357.18 ccw(c2109.56,345.56) 2109.56,362 ccw(c2109.56,378.44) v1@2121.18,366.82
  Bottom Layer w10: v1(1700,1048) 1747,1095 C17.1@1747,1102 ; v1@1700,1054.81 ccw(c1700,1071.25) 1711.63,1059.63 ccw(c1723.25,1048) v1@1706.81,1048 ; 1722.42,1070.42 ccw(c1690.84,1102) C17.1@1735.5,1102 ; C17.1@1736.9,1084.9 cw(c1748,1073.81) C17.1@1748,1089.5 ; C17.1@1748,1102 C19.1@1831,1102 C36.1@1914,1102 ; C17.1@1756.84,1093.16 cw(c1778.18,1071.82) 1778.18,1102 cw(c1778.18,1132.18) C17.1@1756.84,1110.84 ; C19.1@1822.16,1093.16 ccw(c1800.82,1071.82) 1800.82,1102 ccw(c1800.82,1132.18) C19.1@1822.16,1110.84 ; C19.1@1839.84,1093.16 cw(c1861.18,1071.82) 1861.18,1102 cw(c1861.18,1132.18) C19.1@1839.84,1110.84 ; C36.1@1905.16,1093.16 ccw(c1883.82,1071.82) 1883.82,1102 ccw(c1883.82,1132.18) C36.1@1905.16,1110.84 ; C36.1@1914,1089.5 cw(c1914,1059.32) 1935.34,1080.66 cw(c1956.68,1102) C36.1@1926.5,1102 ; C36.1@1918.5,1098.5 1915,1102 C36.1@1914,1102 ; R13.1@1927.16,1028.84 ccw(c1905.82,1050.18) 1936,1050.18 ccw(c1966.18,1050.18) R13.1@1944.84,1028.84 ; R13.1@1936,1007.5 cw(c1936,979.74) 1955.63,999.37 ; R13.1@1948.5,1020 ccw(c1981.09,1020) 1958.05,996.95 ; v1@2019.19,390 ccw(c2002.75,390) 2014.37,401.63 ccw(c2026,413.25) v1@2026,396.81 ; v1(2026,390) 1999,417 1999,540 1898,641 1898,835 1989,926 1989,966 1944,1011 1936,1011 1936,1080 C36.1@1914,1102 ; v1@2127,362 R27.1@2165,362 ; v1@2130.82,357.18 cw(c2142.45,345.55) 2142.45,362 cw(c2142.44,378.44) v1@2130.82,366.82 ; R27.1@2156.16,353.16 ccw(c2134.82,331.82) 2134.82,362 ccw(c2134.82,392.18) R27.1@2156.16,370.84
  Bottom Layer w20: C17.1@1746,1102 1747,1102 C17.1@1748,1102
